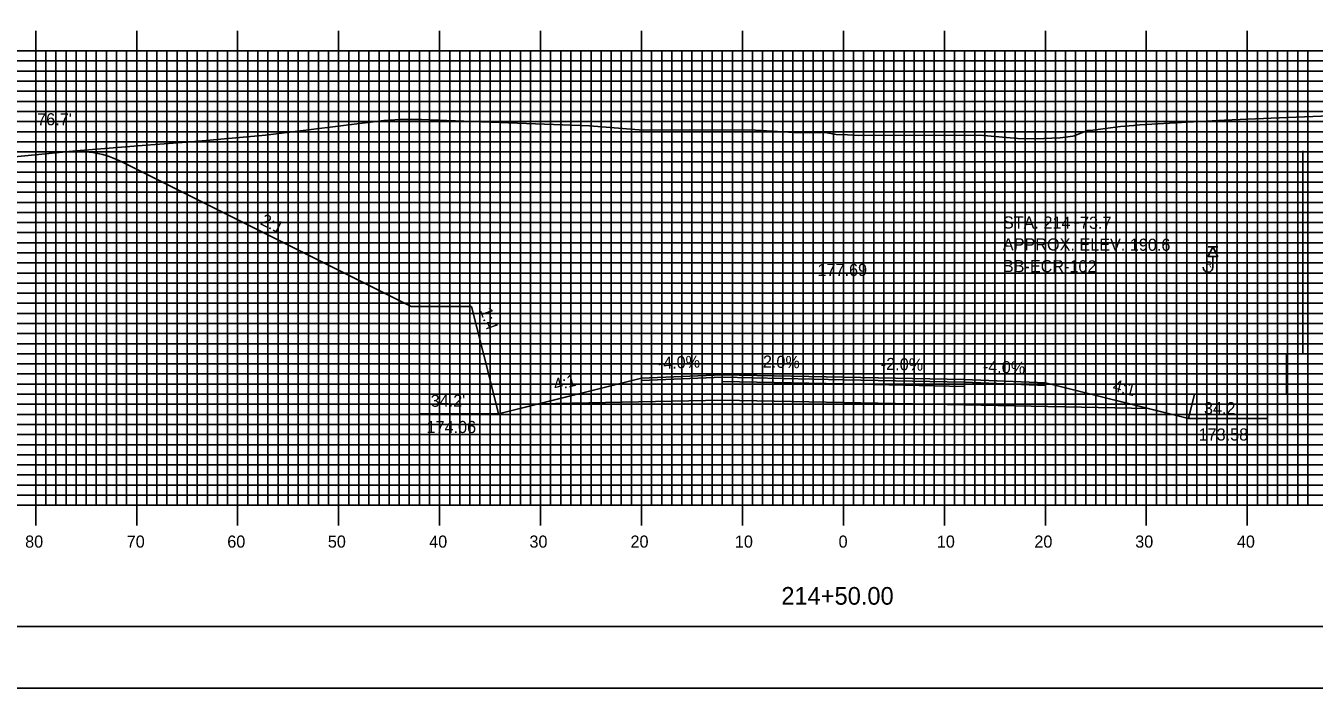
# Model space of a CAD drawing. Extents: x 1796027 to 1796370, y 442591 to 442811.
# Drawn here: x 1796111.4 to 1796239, y 442590.5 to 442656.2 of the extents above; entities that cross this region are included whole.
import ezdxf

# ---------------------------------------------------------------- set-up
doc = ezdxf.new("R2010")
doc.units = 0
for name, color, linetype in [('ANNOTATION', 7, 'Continuous'), ('BORDER', 7, 'Continuous'), ('BORING - REFUSAL', 7, 'Continuous'), ('D_Roadway_Centerline', 7, 'Continuous'), ('D_Roadway_Centerline_Text', 7, 'Continuous'), ('D_Roadway_Edge_Shoulder', 7, 'Continuous'), ('D_Roadway_Edge_TW', 7, 'Continuous'), ('D_Roadway_Pavement', 7, 'Continuous'), ('D_Roadway_SlopeLines', 7, 'Continuous'), ('D_Roadway_SubGrade', 7, 'Continuous'), ('D_Text_Standard', 7, 'Continuous'), ('H_V ANNOTATION', 7, 'Continuous'), ('MAJOR', 7, 'Continuous'), ('MINOR', 7, 'Continuous'), ('PDRAIN', 7, 'Continuous'), ('PLOT BOUNDARY', 7, 'Continuous'), ('S_Roadway_Centerline', 7, 'Continuous')]:
    doc.layers.add(name, color=color, linetype=linetype)

msp = doc.modelspace()

# ---------------------------------------------------------------- linework, layer by layer
at = {"layer": 'ANNOTATION'}
for p, q in [((1796237.89, 442623.67), (1796237.89, 442643.77)), ((1796157.22, 442621.73), (1796155.56, 442628.37)), ((1796236.29, 442619.67), (1796236.29, 442623.67)), ((1796236.29, 442623.67), (1796237.89, 442623.67)), ((1796158.22, 442617.73), (1796157.22, 442621.73)), ((1796226.57, 442617.25), (1796227.17, 442619.67))]:
    msp.add_line(p, q, dxfattribs=at)
msp.add_lwpolyline([(1796236.29, 442619.67), (1796227.17, 442619.67)], dxfattribs=at)
msp.add_arc((1796116.46, 442633.73), 10, 63.4349, 94.5765, dxfattribs=at)
msp.add_arc((1796116.46, 442633.73), 10, 63.4349, 94.5765, dxfattribs=at)
at = {"layer": 'BORDER'}
msp.add_lwpolyline([(1796042.79, 442596.67), (1796362.79, 442596.67), (1796362.79, 442806.67), (1796042.79, 442806.67)], close=True, dxfattribs=at)
at = {"layer": 'BORING - REFUSAL'}
for p, q in [((1796229.47, 442634.27), (1796228.51, 442634.27)), ((1796228.99, 442633.31), (1796228.99, 442632.25))]:
    msp.add_line(p, q, dxfattribs=at)
msp.add_lwpolyline([(1796228.99, 442634.27), (1796229.47, 442633.31), (1796228.51, 442633.31)], close=True, dxfattribs=at)
msp.add_arc((1796228.51, 442632.25), 0.485, 180, 0, dxfattribs=at)
at = {"layer": 'D_Roadway_Centerline'}
msp.add_lwpolyline([(1796158.22, 442617.73), (1796162.22, 442618.73), (1796172.39, 442621.27), (1796180.39, 442621.59), (1796192.39, 442621.35), (1796204.39, 442621.11), (1796212.39, 442620.79), (1796222.57, 442618.25), (1796226.57, 442617.25)], dxfattribs=at)
at = {"layer": 'D_Roadway_Edge_Shoulder'}
for points in [[(1796180.39, 442621.59), (1796172.39, 442621.27), (1796172.39, 442621.02), (1796180.39, 442621.34)], [(1796204.39, 442621.11), (1796212.39, 442620.79), (1796212.39, 442620.54), (1796204.39, 442620.86)]]:
    msp.add_lwpolyline(points, close=True, dxfattribs=at)
at = {"layer": 'D_Roadway_Edge_TW'}
msp.add_lwpolyline([(1796180.39, 442621.34), (1796180.39, 442621.59), (1796192.39, 442621.35), (1796204.39, 442621.11), (1796204.39, 442620.86), (1796192.39, 442621.1)], close=True, dxfattribs=at)
at = {"layer": 'D_Roadway_Pavement'}
msp.add_lwpolyline([(1796180.39, 442620.92), (1796180.39, 442621.34), (1796192.39, 442621.1), (1796204.39, 442620.86), (1796204.39, 442620.44), (1796192.39, 442620.68)], close=True, dxfattribs=at)
at = {"layer": 'D_Roadway_SlopeLines'}
for points in [[(1796155.56, 442628.37), (1796149.56, 442628.37), (1796120.93, 442642.68)], [(1796172.39, 442621.27), (1796158.22, 442617.73)], [(1796212.39, 442620.79), (1796226.57, 442617.25)]]:
    msp.add_lwpolyline(points, dxfattribs=at)
at = {"layer": 'D_Roadway_SubGrade'}
msp.add_lwpolyline([(1796180.39, 442619.09), (1796162.22, 442618.73), (1796172.39, 442621.27), (1796172.39, 442621.02), (1796180.39, 442621.34), (1796192.39, 442621.1), (1796204.39, 442620.86), (1796212.39, 442620.54), (1796212.39, 442620.79), (1796222.57, 442618.25), (1796204.39, 442618.61), (1796192.39, 442618.85)], close=True, dxfattribs=at)
at = {"layer": 'MAJOR'}
for p, q in [((1796112.39, 442655.67), (1796112.39, 442653.67)), ((1796122.39, 442655.67), (1796122.39, 442653.67)), ((1796132.39, 442655.67), (1796132.39, 442653.67)), ((1796142.39, 442655.67), (1796142.39, 442653.67)), ((1796152.39, 442655.67), (1796152.39, 442653.67)), ((1796162.39, 442655.67), (1796162.39, 442653.67)), ((1796172.39, 442655.67), (1796172.39, 442653.67)), ((1796182.39, 442655.67), (1796182.39, 442653.67)), ((1796192.39, 442655.67), (1796192.39, 442653.67)), ((1796202.39, 442655.67), (1796202.39, 442653.67)), ((1796212.39, 442655.67), (1796212.39, 442653.67)), ((1796222.39, 442655.67), (1796222.39, 442653.67)), ((1796232.39, 442655.67), (1796232.39, 442653.67)), ((1796052.39, 442653.67), (1796332.39, 442653.67)), ((1796052.39, 442653.67), (1796332.39, 442653.67)), ((1796112.39, 442608.67), (1796112.39, 442653.67)), ((1796122.39, 442608.67), (1796122.39, 442653.67)), ((1796132.39, 442608.67), (1796132.39, 442653.67)), ((1796142.39, 442608.67), (1796142.39, 442653.67)), ((1796152.39, 442608.67), (1796152.39, 442653.67)), ((1796162.39, 442608.67), (1796162.39, 442653.67)), ((1796172.39, 442608.67), (1796172.39, 442653.67)), ((1796182.39, 442608.67), (1796182.39, 442653.67)), ((1796192.39, 442608.67), (1796192.39, 442653.67)), ((1796202.39, 442608.67), (1796202.39, 442653.67)), ((1796212.39, 442608.67), (1796212.39, 442653.67)), ((1796222.39, 442608.67), (1796222.39, 442653.67)), ((1796232.39, 442608.67), (1796232.39, 442653.67)), ((1796052.39, 442648.67), (1796332.39, 442648.67)), ((1796052.39, 442643.67), (1796332.39, 442643.67)), ((1796052.39, 442638.67), (1796332.39, 442638.67)), ((1796052.39, 442633.67), (1796332.39, 442633.67)), ((1796052.39, 442628.67), (1796332.39, 442628.67)), ((1796052.39, 442623.67), (1796332.39, 442623.67)), ((1796052.39, 442618.67), (1796332.39, 442618.67)), ((1796052.39, 442613.67), (1796332.39, 442613.67)), ((1796052.39, 442608.67), (1796332.39, 442608.67)), ((1796052.39, 442608.67), (1796332.39, 442608.67)), ((1796112.39, 442606.66), (1796112.39, 442608.67)), ((1796122.39, 442606.66), (1796122.39, 442608.67)), ((1796132.39, 442606.66), (1796132.39, 442608.67)), ((1796142.39, 442606.66), (1796142.39, 442608.67)), ((1796152.39, 442606.66), (1796152.39, 442608.67)), ((1796162.39, 442606.66), (1796162.39, 442608.67)), ((1796172.39, 442606.66), (1796172.39, 442608.67)), ((1796182.39, 442606.66), (1796182.39, 442608.67)), ((1796192.39, 442606.66), (1796192.39, 442608.67)), ((1796202.39, 442606.66), (1796202.39, 442608.67)), ((1796212.39, 442606.66), (1796212.39, 442608.67)), ((1796222.39, 442606.66), (1796222.39, 442608.67)), ((1796232.39, 442606.66), (1796232.39, 442608.67))]:
    msp.add_line(p, q, dxfattribs=at)
at = {"layer": 'MINOR'}
for p, q in [((1796052.39, 442652.67), (1796332.39, 442652.67)), ((1796113.39, 442608.67), (1796113.39, 442653.67)), ((1796114.39, 442608.67), (1796114.39, 442653.67)), ((1796115.39, 442608.67), (1796115.39, 442653.67)), ((1796116.39, 442608.67), (1796116.39, 442653.67)), ((1796117.39, 442608.67), (1796117.39, 442653.67)), ((1796118.39, 442608.67), (1796118.39, 442653.67)), ((1796119.39, 442608.67), (1796119.39, 442653.67)), ((1796120.39, 442608.67), (1796120.39, 442653.67)), ((1796121.39, 442608.67), (1796121.39, 442653.67)), ((1796123.39, 442608.67), (1796123.39, 442653.67)), ((1796124.39, 442608.67), (1796124.39, 442653.67)), ((1796125.39, 442608.67), (1796125.39, 442653.67)), ((1796126.39, 442608.67), (1796126.39, 442653.67)), ((1796127.39, 442608.67), (1796127.39, 442653.67)), ((1796128.39, 442608.67), (1796128.39, 442653.67)), ((1796129.39, 442608.67), (1796129.39, 442653.67)), ((1796130.39, 442608.67), (1796130.39, 442653.67)), ((1796131.39, 442608.67), (1796131.39, 442653.67)), ((1796133.39, 442608.67), (1796133.39, 442653.67)), ((1796134.39, 442608.67), (1796134.39, 442653.67)), ((1796135.39, 442608.67), (1796135.39, 442653.67)), ((1796136.39, 442608.67), (1796136.39, 442653.67)), ((1796137.39, 442608.67), (1796137.39, 442653.67)), ((1796138.39, 442608.67), (1796138.39, 442653.67)), ((1796139.39, 442608.67), (1796139.39, 442653.67)), ((1796140.39, 442608.67), (1796140.39, 442653.67)), ((1796141.39, 442608.67), (1796141.39, 442653.67)), ((1796143.39, 442608.67), (1796143.39, 442653.67)), ((1796144.39, 442608.67), (1796144.39, 442653.67)), ((1796145.39, 442608.67), (1796145.39, 442653.67)), ((1796146.39, 442608.67), (1796146.39, 442653.67)), ((1796147.39, 442608.67), (1796147.39, 442653.67)), ((1796148.39, 442608.67), (1796148.39, 442653.67)), ((1796149.39, 442608.67), (1796149.39, 442653.67)), ((1796150.39, 442608.67), (1796150.39, 442653.67)), ((1796151.39, 442608.67), (1796151.39, 442653.67)), ((1796153.39, 442608.67), (1796153.39, 442653.67)), ((1796154.39, 442608.67), (1796154.39, 442653.67)), ((1796155.39, 442608.67), (1796155.39, 442653.67)), ((1796156.39, 442608.67), (1796156.39, 442653.67)), ((1796157.39, 442608.67), (1796157.39, 442653.67)), ((1796158.39, 442608.67), (1796158.39, 442653.67)), ((1796159.39, 442608.67), (1796159.39, 442653.67)), ((1796160.39, 442608.67), (1796160.39, 442653.67)), ((1796161.39, 442608.67), (1796161.39, 442653.67)), ((1796163.39, 442608.67), (1796163.39, 442653.67)), ((1796164.39, 442608.67), (1796164.39, 442653.67)), ((1796165.39, 442608.67), (1796165.39, 442653.67)), ((1796166.39, 442608.67), (1796166.39, 442653.67)), ((1796167.39, 442608.67), (1796167.39, 442653.67)), ((1796168.39, 442608.67), (1796168.39, 442653.67)), ((1796169.39, 442608.67), (1796169.39, 442653.67)), ((1796170.39, 442608.67), (1796170.39, 442653.67)), ((1796171.39, 442608.67), (1796171.39, 442653.67)), ((1796173.39, 442608.67), (1796173.39, 442653.67)), ((1796174.39, 442608.67), (1796174.39, 442653.67)), ((1796175.39, 442608.67), (1796175.39, 442653.67)), ((1796176.39, 442608.67), (1796176.39, 442653.67)), ((1796177.39, 442608.67), (1796177.39, 442653.67)), ((1796178.39, 442608.67), (1796178.39, 442653.67)), ((1796179.39, 442608.67), (1796179.39, 442653.67)), ((1796180.39, 442608.67), (1796180.39, 442653.67)), ((1796181.39, 442608.67), (1796181.39, 442653.67)), ((1796183.39, 442608.67), (1796183.39, 442653.67)), ((1796184.39, 442608.67), (1796184.39, 442653.67)), ((1796185.39, 442608.67), (1796185.39, 442653.67)), ((1796186.39, 442608.67), (1796186.39, 442653.67)), ((1796187.39, 442608.67), (1796187.39, 442653.67)), ((1796188.39, 442608.67), (1796188.39, 442653.67)), ((1796189.39, 442608.67), (1796189.39, 442653.67)), ((1796190.39, 442608.67), (1796190.39, 442653.67)), ((1796191.39, 442608.67), (1796191.39, 442653.67)), ((1796193.39, 442608.67), (1796193.39, 442653.67)), ((1796194.39, 442608.67), (1796194.39, 442653.67)), ((1796195.39, 442608.67), (1796195.39, 442653.67)), ((1796196.39, 442608.67), (1796196.39, 442653.67)), ((1796197.39, 442608.67), (1796197.39, 442653.67)), ((1796198.39, 442608.67), (1796198.39, 442653.67)), ((1796199.39, 442608.67), (1796199.39, 442653.67)), ((1796200.39, 442608.67), (1796200.39, 442653.67)), ((1796201.39, 442608.67), (1796201.39, 442653.67)), ((1796203.39, 442608.67), (1796203.39, 442653.67)), ((1796204.39, 442608.67), (1796204.39, 442653.67)), ((1796205.39, 442608.67), (1796205.39, 442653.67)), ((1796206.39, 442608.67), (1796206.39, 442653.67)), ((1796207.39, 442608.67), (1796207.39, 442653.67)), ((1796208.39, 442608.67), (1796208.39, 442653.67)), ((1796209.39, 442608.67), (1796209.39, 442653.67)), ((1796210.39, 442608.67), (1796210.39, 442653.67)), ((1796211.39, 442608.67), (1796211.39, 442653.67)), ((1796213.39, 442608.67), (1796213.39, 442653.67)), ((1796214.39, 442608.67), (1796214.39, 442653.67)), ((1796215.39, 442608.67), (1796215.39, 442653.67)), ((1796216.39, 442608.67), (1796216.39, 442653.67)), ((1796217.39, 442608.67), (1796217.39, 442653.67)), ((1796218.39, 442608.67), (1796218.39, 442653.67)), ((1796219.39, 442608.67), (1796219.39, 442653.67)), ((1796220.39, 442608.67), (1796220.39, 442653.67)), ((1796221.39, 442608.67), (1796221.39, 442653.67)), ((1796223.39, 442608.67), (1796223.39, 442653.67)), ((1796224.39, 442608.67), (1796224.39, 442653.67)), ((1796225.39, 442608.67), (1796225.39, 442653.67)), ((1796226.39, 442608.67), (1796226.39, 442653.67)), ((1796227.39, 442617.25), (1796227.39, 442653.67)), ((1796228.39, 442608.67), (1796228.39, 442653.67)), ((1796229.39, 442608.67), (1796229.39, 442653.67)), ((1796230.39, 442608.67), (1796230.39, 442653.67)), ((1796231.39, 442608.67), (1796231.39, 442653.67)), ((1796233.39, 442608.67), (1796233.39, 442653.67)), ((1796234.39, 442608.67), (1796234.39, 442653.67)), ((1796235.39, 442608.67), (1796235.39, 442653.67)), ((1796236.39, 442608.67), (1796236.39, 442653.67)), ((1796237.39, 442608.67), (1796237.39, 442653.67)), ((1796238.39, 442608.67), (1796238.39, 442653.67)), ((1796052.39, 442651.67), (1796332.39, 442651.67)), ((1796052.39, 442650.67), (1796332.39, 442650.67)), ((1796052.39, 442649.67), (1796332.39, 442649.67)), ((1796052.39, 442647.67), (1796332.39, 442647.67)), ((1796052.39, 442646.67), (1796332.39, 442646.67)), ((1796052.39, 442645.67), (1796332.39, 442645.67)), ((1796052.39, 442644.67), (1796332.39, 442644.67)), ((1796052.39, 442642.67), (1796332.39, 442642.67)), ((1796052.39, 442641.67), (1796332.39, 442641.67)), ((1796052.39, 442640.67), (1796332.39, 442640.67)), ((1796052.39, 442639.67), (1796332.39, 442639.67)), ((1796052.39, 442637.67), (1796332.39, 442637.67)), ((1796052.39, 442636.67), (1796332.39, 442636.67)), ((1796052.39, 442635.67), (1796332.39, 442635.67)), ((1796052.39, 442634.67), (1796332.39, 442634.67)), ((1796052.39, 442632.67), (1796332.39, 442632.67)), ((1796052.39, 442631.67), (1796332.39, 442631.67)), ((1796052.39, 442630.67), (1796332.39, 442630.67)), ((1796052.39, 442629.67), (1796332.39, 442629.67)), ((1796052.39, 442627.67), (1796332.39, 442627.67)), ((1796052.39, 442626.67), (1796332.39, 442626.67)), ((1796052.39, 442625.67), (1796332.39, 442625.67)), ((1796052.39, 442624.67), (1796332.39, 442624.67)), ((1796052.39, 442622.67), (1796332.39, 442622.67)), ((1796052.39, 442621.67), (1796332.39, 442621.67)), ((1796052.39, 442620.67), (1796332.39, 442620.67)), ((1796052.39, 442619.67), (1796332.39, 442619.67)), ((1796052.39, 442617.67), (1796332.39, 442617.67)), ((1796227.39, 442608.67), (1796227.39, 442617.25)), ((1796052.39, 442616.67), (1796332.39, 442616.67)), ((1796052.39, 442615.67), (1796332.39, 442615.67)), ((1796052.39, 442614.67), (1796332.39, 442614.67)), ((1796052.39, 442612.67), (1796332.39, 442612.67)), ((1796052.39, 442611.67), (1796332.39, 442611.67)), ((1796052.39, 442610.67), (1796332.39, 442610.67)), ((1796052.39, 442609.67), (1796332.39, 442609.67))]:
    msp.add_line(p, q, dxfattribs=at)
at = {"layer": 'PDRAIN'}
for p, q in [((1796150.35, 442617.73), (1796158.22, 442617.73)), ((1796226.57, 442617.25), (1796234.3, 442617.25))]:
    msp.add_line(p, q, dxfattribs=at)
at = {"layer": 'PLOT BOUNDARY'}
msp.add_lwpolyline([(1796026.61, 442590.55), (1796366.61, 442590.55), (1796366.61, 442810.55), (1796026.61, 442810.55)], close=True, dxfattribs=at)
at = {"layer": 'S_Roadway_Centerline'}
msp.add_lwpolyline([(1796108.9, 442643.03), (1796111.65, 442643.31), (1796116.39, 442643.77), (1796123.32, 442644.33), (1796127.78, 442644.67), (1796135.14, 442645.33), (1796146.86, 442646.77), (1796148.47, 442646.88), (1796150.6, 442646.87), (1796155.64, 442646.67), (1796167.23, 442646.26), (1796172.54, 442645.83), (1796177.16, 442645.86), (1796183.67, 442645.82), (1796187.5, 442645.59), (1796190.77, 442645.55), (1796191.67, 442645.39), (1796192.8, 442645.36), (1796193.9, 442645.3), (1796205.9, 442645.31), (1796209.65, 442645), (1796211.4, 442644.95), (1796213.86, 442645.06), (1796215.1, 442645.24), (1796215.23, 442645.26), (1796216.55, 442645.77), (1796216.86, 442645.8), (1796219.84, 442646.19), (1796221.11, 442646.29), (1796221.2, 442646.29), (1796221.44, 442646.31), (1796221.75, 442646.35), (1796226.47, 442646.6), (1796230.15, 442646.82), (1796234.75, 442647), (1796243.02, 442647.33)], dxfattribs=at)

# ---------------------------------------------------------------- texts
at = {"layer": 'ANNOTATION'}
for s, rotation, p in [('2:1', 333.4349, (1796134.55, 442636.52)), ('2:1', 333.4349, (1796134.55, 442636.52)), ('1:4', 289.484, (1796156.36, 442628)), ('-4.0%', 2.2906, (1796174.02, 442622.14)), ('2.0%', 358.8542, (1796184.4, 442622.31)), ('-2.0%', 358.8542, (1796196.08, 442622.08)), ('-4.0%', 357.7094, (1796206.18, 442621.84)), ('4:1', 14.0362, (1796163.84, 442619.99)), ('4:1', 345.9638, (1796218.98, 442620))]:
    msp.add_text(s, height=1.2, rotation=rotation, dxfattribs=at).set_placement(p)
for s, p in [("34.2'", (1796151.51, 442618.42)), ("34.2'", (1796228.1, 442617.68)), ('174.06', (1796151.1, 442615.82)), ('173.58', (1796227.57, 442615.08))]:
    msp.add_text(s, height=1.2, dxfattribs=at).set_placement(p)
at = {"layer": 'BORING - REFUSAL'}
for s, p in [('STA. 214+73.7', (1796208.19, 442636.08)), ('APPROX. ELEV. 190.6', (1796208.18, 442633.92)), ('BB-ECR-102', (1796208.18, 442631.76))]:
    msp.add_text(s, height=1.2, rotation=359.8142, dxfattribs=at).set_placement(p)
msp.add_text('R', height=0.64, dxfattribs=at).set_placement((1796228.28, 442632.19))
at = {"layer": 'D_Roadway_Centerline'}
for s, p in [('C', (1796192.39, 442621.35)), ('L', (1796192.39, 442621.34))]:
    msp.add_text(s, height=0.0146, dxfattribs=at).set_placement(p)
at = {"layer": 'D_Roadway_Centerline_Text'}
msp.add_text('177.69', height=1.2, dxfattribs=at).set_placement((1796189.82, 442631.38))
at = {"layer": 'D_Text_Standard'}
msp.add_text("76.7'", height=1.2, dxfattribs=at).set_placement((1796112.53, 442646.3))
at = {"layer": 'H_V ANNOTATION'}
for s, height, p in [('80', 1.2, (1796111.34, 442604.47)), ('70', 1.2, (1796121.4, 442604.47)), ('60', 1.2, (1796131.36, 442604.47)), ('50', 1.2, (1796141.32, 442604.47)), ('40', 1.2, (1796151.36, 442604.47)), ('30', 1.2, (1796161.29, 442604.47)), ('20', 1.2, (1796171.3, 442604.47)), ('10', 1.2, (1796181.64, 442604.47)), ('0', 1.2, (1796191.91, 442604.47)), ('10', 1.2, (1796201.64, 442604.47)), ('20', 1.2, (1796211.3, 442604.47)), ('30', 1.2, (1796221.29, 442604.47)), ('40', 1.2, (1796231.36, 442604.47)), ('214+50.00', 1.75, (1796186.24, 442598.82))]:
    msp.add_text(s, height=height, dxfattribs=at).set_placement(p)

doc.saveas('drawing.dxf')
